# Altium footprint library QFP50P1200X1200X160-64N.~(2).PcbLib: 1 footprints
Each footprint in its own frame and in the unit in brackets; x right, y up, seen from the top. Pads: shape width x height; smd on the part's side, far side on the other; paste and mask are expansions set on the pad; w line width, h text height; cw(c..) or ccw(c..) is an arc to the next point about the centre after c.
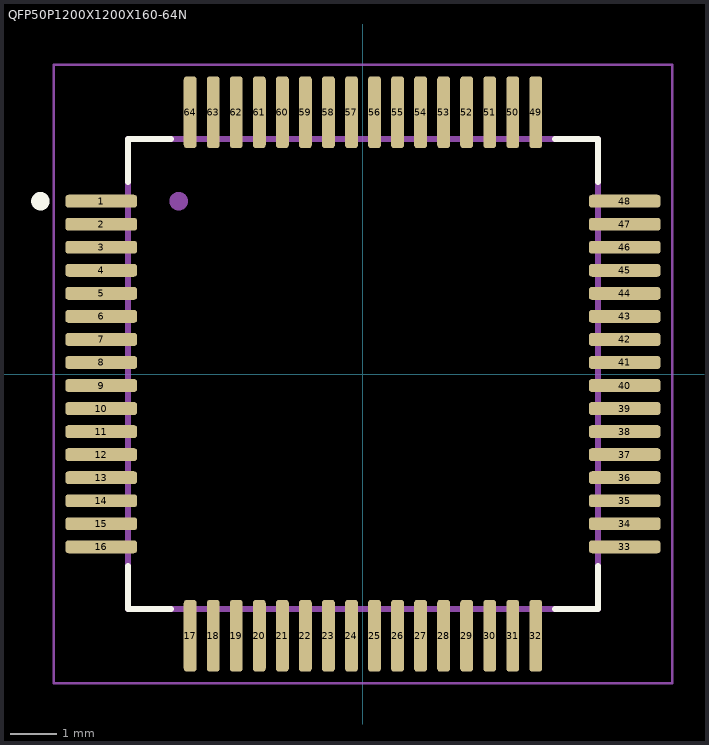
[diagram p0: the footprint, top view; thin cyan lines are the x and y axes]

## QFP50P1200X1200X160-64N [mm]
pads (64):
  rrect50% 1.56x0.28 smd: 1(-5.68,3.75) 2(-5.68,3.25) 3(-5.68,2.75) 4(-5.68,2.25) 5(-5.68,1.75) 6(-5.68,1.25) 7(-5.68,0.75) 8(-5.68,0.25) 9(-5.68,-0.25) 10(-5.68,-0.75) 11(-5.68,-1.25) 12(-5.68,-1.75) 13(-5.68,-2.25) 14(-5.68,-2.75) 15(-5.68,-3.25) 16(-5.68,-3.75) 33(5.68,-3.75) 34(5.68,-3.25) 35(5.68,-2.75) 36(5.68,-2.25) 37(5.68,-1.75) 38(5.68,-1.25) 39(5.68,-0.75) 40(5.68,-0.25) 41(5.68,0.25) 42(5.68,0.75) 43(5.68,1.25) 44(5.68,1.75) 45(5.68,2.25) 46(5.68,2.75) 47(5.68,3.25) 48(5.68,3.75)
  rrect50% 0.28x1.56 smd: 17(-3.75,-5.68) 18(-3.25,-5.68) 19(-2.75,-5.68) 20(-2.25,-5.68) 21(-1.75,-5.68) 22(-1.25,-5.68) 23(-0.75,-5.68) 24(-0.25,-5.68) 25(0.25,-5.68) 26(0.75,-5.68) 27(1.25,-5.68) 28(1.75,-5.68) 29(2.25,-5.68) 30(2.75,-5.68) 31(3.25,-5.68) 32(3.75,-5.68) 49(3.75,5.68) 50(3.25,5.68) 51(2.75,5.68) 52(2.25,5.68) 53(1.75,5.68) 54(1.25,5.68) 55(0.75,5.68) 56(0.25,5.68) 57(-0.25,5.68) 58(-0.75,5.68) 59(-1.25,5.68) 60(-1.75,5.68) 61(-2.25,5.68) 62(-2.75,5.68) 63(-3.25,5.68) 64(-3.75,5.68)
Top Overlay:
  circle w0.2: c-7,3.75 r0.1
  lines w0.127: -5.1,-4.17 -5.1,-5.1 -4.17,-5.1 ; -5.1,4.17 -5.1,5.1 -4.17,5.1 ; 4.17,-5.1 5.1,-5.1 5.1,-4.17 ; 4.17,5.1 5.1,5.1 5.1,4.17
Mechanical 13:
  circle w0.2: c-4,3.75 r0.1
  lines w0.127: -5.1,-5.1 -5.1,5.1 5.1,5.1 5.1,-5.1 -5.1,-5.1
Mechanical 15:
  lines w0.05: -6.71,-6.71 -6.71,6.71 6.71,6.71 6.71,-6.71 -6.71,-6.71
3D body "STM32F446RET7.STEP": height 6, standoff -6, extent -1.016,-6.127 0.584,5.873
